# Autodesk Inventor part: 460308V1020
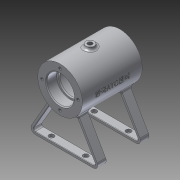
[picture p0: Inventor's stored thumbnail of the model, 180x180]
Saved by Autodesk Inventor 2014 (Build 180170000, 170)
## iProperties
Created: 2016-03
Part Number: 460308V1020
Material: 알루미늄 6061
Document SubType Name: Modeling
Designer: 703-15
Density: 2.71 g/cm^3
Appearance: 알루미늄 - 평지
Mass: 213.529 g
Surface Area: 336.749 cm^2
Volume: 78.7931 cm^3
Author: 703-15
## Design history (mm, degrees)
sketch "스케치4"
  geometry: L1 (16.613, -20)-(42.594, -65); L2 (-16.613, -20)-(-42.594, -65); L3 (0, 0)-(0, -4.858); L4 (-42.594, -65)-(42.594, -65); L5 (-16.613, -20)-(16.613, -20); A1 r 26 centre (0, 0) between (16.613, -20) and (-16.613, -20)
  constraints: 10 end point, 2 point on circle, 1 centre point, 1 coincident, 1 horizontal alignment, 1 parallel, 1 perpendicular, 1 vertical
  dimensions: "d14" = 30 deg angle of L2 L3; "d15" = 60 deg angle of L1 L2; "d16" = 65 distance from line of L3.start L4; "d17" = 52 diameter of A1; "d18" = 45 vertical distance of L1.end L1.start
extrude "돌출1" new body sketch "스케치4" distance "d19" = 10; taper "d20" = 0 deg
node "작업 평면3"
fillet "모깎기1" dims "d22" = 5
feature "쉘1" dims "d23" = 3
sketch "스케치6"
  geometry: L1 (-55, 26)-(15, 26); L2 (15, 26)-(15, 0); L3 (15, 0)-(-55, 0); L4 (-55, 0)-(-55, 26); L5 (0, -57.5)-(0, -20) reference; L6 (-20, 26)-(-20, 0); 1 further point
  constraints: 10 end point, 2 midpoint, 2 parallel, 1 horizontal, 1 perpendicular, 1 point on line
  dimensions: "d24" = 70 distance of L1.start L1.end; "d25" = 20 distance between parallel lines of L5 L6; "d26" = 26 distance of L1.end L2.end
revolve "회전2" sketch "스케치6" stored, may be unused: angle "d27" = 90 deg
fillet "모깎기2" dims "d38" = 3
node "작업 평면5"
  node "작업 평면4"
sketch "스케치8"
  geometry: L1 (15, -26)-(15, 26) reference; C1 r 6 at (-20, 0); 1 further point
  constraints: 1 centre point, 1 horizontal alignment
  dimensions: "d41" = 35 distance from line of L1 C1.centre; "d42" = 12 diameter of C1
extrude "돌출2" join sketch "스케치8" stored distance "d43" = 10; taper "d44" = 0 deg
hole "구멍2" diameter "d47" = 28; stored, may be unused: countersink angle "d51" = 90 deg, drill point angle "d53" = 118 deg; dims "d45" = 10, "d46" = 10, "d48" = 6, "d49" = 4, "d50" = 2, "d52" = 8
sketch "스케치9"
  geometry: L1 (-38, 21)-(-2, 21); L2 (1, 18)-(1, 0); L3 (1, 0)-(-41, 0); L4 (-41, 0)-(-41, 18); L5 (15, 14)-(15, -14) reference; A1 r 3 centre (-38, 18) between (-38, 21) and (-41, 18); A2 r 3 centre (-2, 18) between (1, 18) and (-2, 21); 3 further points
  constraints: 8 end point, 4 point on circle, 4 point on line, 4 tangent, 2 centre point, 2 parallel, 1 equal radius, 1 horizontal, 1 horizontal alignment, 1 perpendicular
  dimensions: "d54" = 42 distance of point (-41, 21) point (1, 21); "d55" = 21 distance of point (1, 21) L2.end; "d56" = 14 distance between parallel lines of L5 L2; "d57" = 3 radius of A1
revolve "회전3" sketch "스케치9" stored, may be unused: angle "d58" = 90 deg
hole "구멍3" diameter "d61" = 32; stored, may be unused: countersink angle "d65" = 90 deg, drill point angle "d67" = 0 deg; dims "d59" = 10, "d60" = 10, "d62" = 6, "d63" = 4, "d64" = 2, "d66" = 12
chamfer "모따기1" distance "d68" = 1; stored, may be unused: second distance "d69" = 2, angle "d70" = 45 deg
fillet "모깎기3" dims "d71" = 0.3
sketch "스케치10"
  geometry: C1 r 26 at (0, 0) reference; 1 further point
  constraints: 1 vertical alignment
  dimensions: "d72" = 21 distance of C1.centre point (0, 21)
hole "구멍4" sketch "스케치10" at (0, 21) diameter "d73" = 3.459; stored, may be unused: countersink angle "d77" = 90 deg, drill point angle "d79" = 118 deg; dims "d74" = 8, "d75" = 4, "d76" = 2, "d78" = 10
hole "구멍5" diameter "d85" = 5.188; stored, may be unused: countersink angle "d89" = 90 deg, drill point angle "d91" = 118 deg; dims "d83" = 10, "d84" = 10, "d86" = 8, "d87" = 4, "d88" = 2, "d90" = 10
fillet "모깎기4" dims "d92" = 3
node "작업 평면6"
sketch "스케치11"
  geometry: L1 (26, 15)-(-26, 15) reference; C1 r 5 at (0, -20); 1 further point
  constraints: 1 centre point, 1 vertical alignment
  dimensions: "d94" = 35 distance from line of L1 C1.centre; "d95" = 10 diameter of C1
extrude "돌출3" join sketch "스케치11" stored distance "d96" = 10; taper "d97" = 0 deg
fillet "모깎기5" dims "d98" = 3
hole "구멍6" diameter "d101" = 5.188; stored, may be unused: countersink angle "d105" = 90 deg, drill point angle "d107" = 118 deg; dims "d99" = 10, "d100" = 10, "d102" = 8, "d103" = 4, "d104" = 2, "d106" = 10
node "작업 평면7"
sketch "스케치12"
  geometry: L1 (-55, -26)-(-55, 26) reference; 2 further points
  constraints: 1 horizontal alignment, 1 other
  dimensions: "d109" = 35 distance from line of point (-20, 0) L1
feature "엠보싱1" sketch "스케치12" dims "d14" = 30 deg, "d15" = 60 deg, "d16" = 65, "d17" = 52, "d18" = 45, "d110" = 0.5, "d111" = 0
fillet "모깎기6" dims "d112" = 0.5
fillet "모깎기7" dims "d113" = 0.5
sketch "스케치14"
  geometry: L1 (0, 10)-(67.868, 10) reference; C1 r 3 at (53.934, 5); C2 r 3 at (13.934, 5); 1 further point
  constraints: 2 centre point, 1 equal radius, 1 horizontal alignment
  dimensions: "d124" = 6 diameter of C1; "d125" = 5 distance from line of L1 C1.centre; "d126" = 20 horizontal distance of point (33.934, 0) C2.centre; "d127" = 40 distance of C1.centre C2.centre
extrude "돌출4" cut sketch "스케치14" stored distance "d128" = 10; taper "d129" = 0 deg
node "솔리드2"
mirror "대칭1"
mirror "대칭3"
pattern_circular "원형 패턴1" dims angle "d81" = 360 deg
mirror "대칭4"
mirror "대칭6"
other parameters: "d39" = 15 deg, "d40" = -29, "d93" = 29, "d108" = 26
